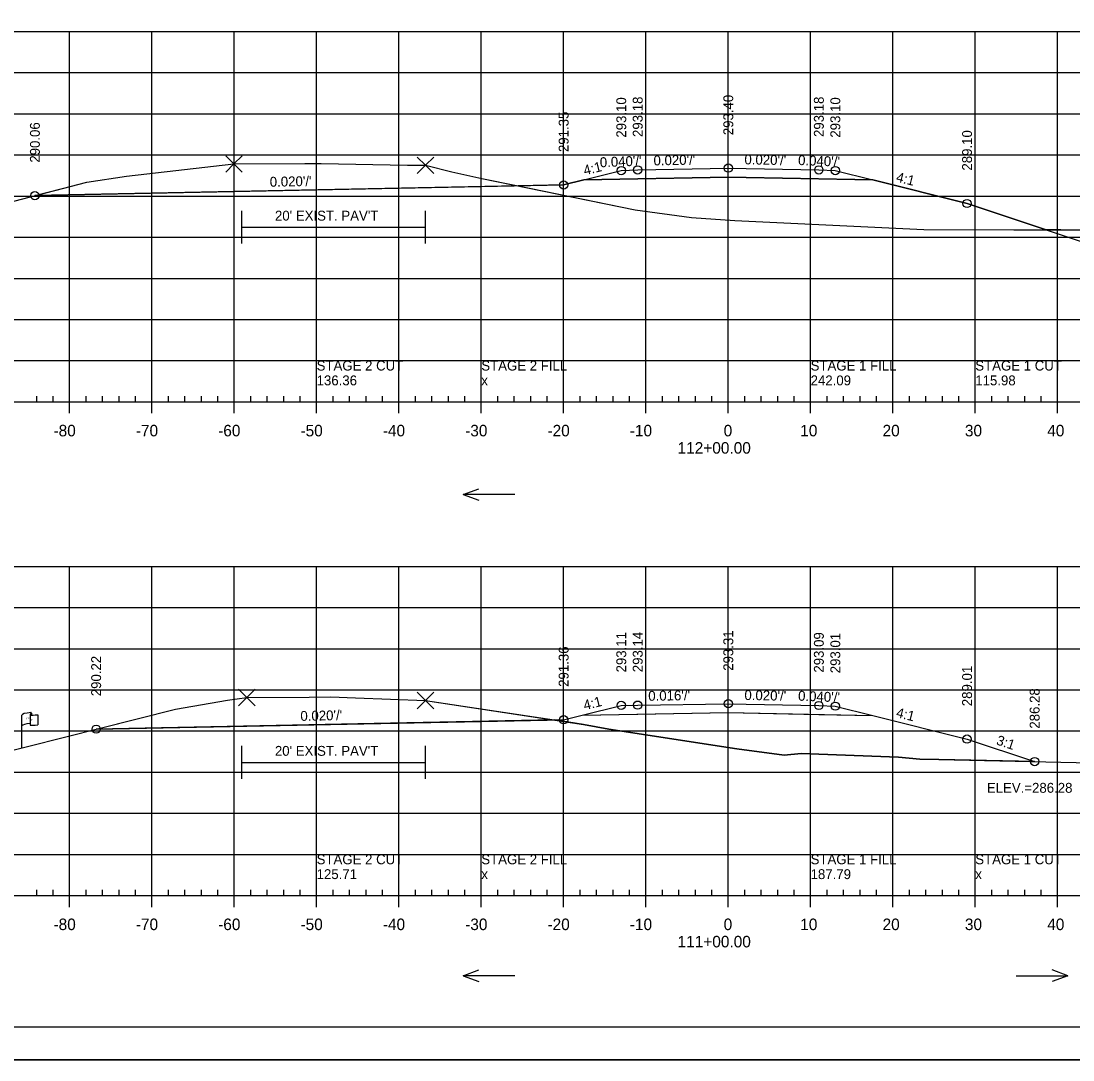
# Model space of a CAD drawing. Extents: x 1370843 to 1371177, y 380307 to 382654.
# Drawn here: x 1370927.8 to 1371055.6, y 381160.8 to 381287.1 of the extents above; entities that cross this region are included whole.
import ezdxf

# ---------------------------------------------------------------- set-up
doc = ezdxf.new("R2010")
doc.units = 0
for name, color, linetype in [('R_Alt Surface', 7, 'Continuous'), ('R_Axis', 7, 'Continuous'), ('R_Axis Annot', 7, 'Continuous'), ('R_Border', 7, 'Continuous'), ('R_Exist Surface', 7, 'Continuous'), ('R_Exist Surface Annot', 7, 'Continuous'), ('R_Fin Surface', 7, 'Continuous'), ('R_Fin Surface Annot', 7, 'Continuous'), ('R_Grid', 7, 'Continuous'), ('R_No Plot', 7, 'Continuous'), ('R_ROW', 7, 'Continuous'), ('R_Water Annot', 7, 'Continuous')]:
    doc.layers.add(name, color=color, linetype=linetype)

msp = doc.modelspace()

# ---------------------------------------------------------------- linework, layer by layer
at = {"layer": 'R_Alt Surface'}
for points in [[(1370996.17, 381267.76), (1371002.71, 381267.89), (1371013.71, 381268.11), (1371024.71, 381267.89), (1371031.25, 381267.76)], [(1370995.96, 381202.72), (1371002.71, 381202.86), (1371013.71, 381203.03), (1371024.71, 381202.81), (1371031.25, 381202.68)]]:
    msp.add_lwpolyline(points, dxfattribs=at)
at = {"layer": 'R_Axis'}
for p, q in [((1370929.71, 381240.8), (1370929.71, 381241.5)), ((1370931.71, 381240.8), (1370931.71, 381241.5)), ((1370935.71, 381240.8), (1370935.71, 381241.5)), ((1370937.71, 381240.8), (1370937.71, 381241.5)), ((1370939.71, 381240.8), (1370939.71, 381241.5)), ((1370941.71, 381240.8), (1370941.71, 381241.5)), ((1370945.71, 381240.8), (1370945.71, 381241.5)), ((1370947.71, 381240.8), (1370947.71, 381241.5)), ((1370949.71, 381240.8), (1370949.71, 381241.5)), ((1370951.71, 381240.8), (1370951.71, 381241.5)), ((1370955.71, 381240.8), (1370955.71, 381241.5)), ((1370957.71, 381240.8), (1370957.71, 381241.5)), ((1370959.71, 381240.8), (1370959.71, 381241.5)), ((1370961.71, 381240.8), (1370961.71, 381241.5)), ((1370965.71, 381240.8), (1370965.71, 381241.5)), ((1370967.71, 381240.8), (1370967.71, 381241.5)), ((1370969.71, 381240.8), (1370969.71, 381241.5)), ((1370971.71, 381240.8), (1370971.71, 381241.5)), ((1370975.71, 381240.8), (1370975.71, 381241.5)), ((1370977.71, 381240.8), (1370977.71, 381241.5)), ((1370979.71, 381240.8), (1370979.71, 381241.5)), ((1370981.71, 381240.8), (1370981.71, 381241.5)), ((1370985.71, 381240.8), (1370985.71, 381241.5)), ((1370987.71, 381240.8), (1370987.71, 381241.5)), ((1370989.71, 381240.8), (1370989.71, 381241.5)), ((1370991.71, 381240.8), (1370991.71, 381241.5)), ((1370995.71, 381240.8), (1370995.71, 381241.5)), ((1370997.71, 381240.8), (1370997.71, 381241.5)), ((1370999.71, 381240.8), (1370999.71, 381241.5)), ((1371001.71, 381240.8), (1371001.71, 381241.5)), ((1371005.71, 381240.8), (1371005.71, 381241.5)), ((1371007.71, 381240.8), (1371007.71, 381241.5)), ((1371009.71, 381240.8), (1371009.71, 381241.5)), ((1371011.71, 381240.8), (1371011.71, 381241.5)), ((1371015.71, 381240.8), (1371015.71, 381241.5)), ((1371017.71, 381240.8), (1371017.71, 381241.5)), ((1371019.71, 381240.8), (1371019.71, 381241.5)), ((1371021.71, 381240.8), (1371021.71, 381241.5)), ((1371025.71, 381240.8), (1371025.71, 381241.5)), ((1371027.71, 381240.8), (1371027.71, 381241.5)), ((1371029.71, 381240.8), (1371029.71, 381241.5)), ((1371031.71, 381240.8), (1371031.71, 381241.5)), ((1371035.71, 381240.8), (1371035.71, 381241.5)), ((1371037.71, 381240.8), (1371037.71, 381241.5)), ((1371039.71, 381240.8), (1371039.71, 381241.5)), ((1371041.71, 381240.8), (1371041.71, 381241.5)), ((1371045.71, 381240.8), (1371045.71, 381241.5)), ((1371047.71, 381240.8), (1371047.71, 381241.5)), ((1371049.71, 381240.8), (1371049.71, 381241.5)), ((1371051.71, 381240.8), (1371051.71, 381241.5)), ((1370868.71, 381240.8), (1371158.71, 381240.8)), ((1370933.71, 381239.4), (1370933.71, 381240.8)), ((1370943.71, 381239.4), (1370943.71, 381240.8)), ((1370953.71, 381239.4), (1370953.71, 381240.8)), ((1370963.71, 381239.4), (1370963.71, 381240.8)), ((1370973.71, 381239.4), (1370973.71, 381240.8)), ((1370983.71, 381239.4), (1370983.71, 381240.8)), ((1370993.71, 381239.4), (1370993.71, 381240.8)), ((1371003.71, 381239.4), (1371003.71, 381240.8)), ((1371013.71, 381239.4), (1371013.71, 381240.8)), ((1371023.71, 381239.4), (1371023.71, 381240.8)), ((1371033.71, 381239.4), (1371033.71, 381240.8)), ((1371043.71, 381239.4), (1371043.71, 381240.8)), ((1371053.71, 381239.4), (1371053.71, 381240.8)), ((1370929.71, 381180.8), (1370929.71, 381181.5)), ((1370931.71, 381180.8), (1370931.71, 381181.5)), ((1370935.71, 381180.8), (1370935.71, 381181.5)), ((1370937.71, 381180.8), (1370937.71, 381181.5)), ((1370939.71, 381180.8), (1370939.71, 381181.5)), ((1370941.71, 381180.8), (1370941.71, 381181.5)), ((1370945.71, 381180.8), (1370945.71, 381181.5)), ((1370947.71, 381180.8), (1370947.71, 381181.5)), ((1370949.71, 381180.8), (1370949.71, 381181.5)), ((1370951.71, 381180.8), (1370951.71, 381181.5)), ((1370955.71, 381180.8), (1370955.71, 381181.5)), ((1370957.71, 381180.8), (1370957.71, 381181.5)), ((1370959.71, 381180.8), (1370959.71, 381181.5)), ((1370961.71, 381180.8), (1370961.71, 381181.5)), ((1370965.71, 381180.8), (1370965.71, 381181.5)), ((1370967.71, 381180.8), (1370967.71, 381181.5)), ((1370969.71, 381180.8), (1370969.71, 381181.5)), ((1370971.71, 381180.8), (1370971.71, 381181.5)), ((1370975.71, 381180.8), (1370975.71, 381181.5)), ((1370977.71, 381180.8), (1370977.71, 381181.5)), ((1370979.71, 381180.8), (1370979.71, 381181.5)), ((1370981.71, 381180.8), (1370981.71, 381181.5)), ((1370985.71, 381180.8), (1370985.71, 381181.5)), ((1370987.71, 381180.8), (1370987.71, 381181.5)), ((1370989.71, 381180.8), (1370989.71, 381181.5)), ((1370991.71, 381180.8), (1370991.71, 381181.5)), ((1370995.71, 381180.8), (1370995.71, 381181.5)), ((1370997.71, 381180.8), (1370997.71, 381181.5)), ((1370999.71, 381180.8), (1370999.71, 381181.5)), ((1371001.71, 381180.8), (1371001.71, 381181.5)), ((1371005.71, 381180.8), (1371005.71, 381181.5)), ((1371007.71, 381180.8), (1371007.71, 381181.5)), ((1371009.71, 381180.8), (1371009.71, 381181.5)), ((1371011.71, 381180.8), (1371011.71, 381181.5)), ((1371015.71, 381180.8), (1371015.71, 381181.5)), ((1371017.71, 381180.8), (1371017.71, 381181.5)), ((1371019.71, 381180.8), (1371019.71, 381181.5)), ((1371021.71, 381180.8), (1371021.71, 381181.5)), ((1371025.71, 381180.8), (1371025.71, 381181.5)), ((1371027.71, 381180.8), (1371027.71, 381181.5)), ((1371029.71, 381180.8), (1371029.71, 381181.5)), ((1371031.71, 381180.8), (1371031.71, 381181.5)), ((1371035.71, 381180.8), (1371035.71, 381181.5)), ((1371037.71, 381180.8), (1371037.71, 381181.5)), ((1371039.71, 381180.8), (1371039.71, 381181.5)), ((1371041.71, 381180.8), (1371041.71, 381181.5)), ((1371045.71, 381180.8), (1371045.71, 381181.5)), ((1371047.71, 381180.8), (1371047.71, 381181.5)), ((1371049.71, 381180.8), (1371049.71, 381181.5)), ((1371051.71, 381180.8), (1371051.71, 381181.5)), ((1370868.71, 381180.8), (1371158.71, 381180.8)), ((1370933.71, 381179.4), (1370933.71, 381180.8)), ((1370943.71, 381179.4), (1370943.71, 381180.8)), ((1370953.71, 381179.4), (1370953.71, 381180.8)), ((1370963.71, 381179.4), (1370963.71, 381180.8)), ((1370973.71, 381179.4), (1370973.71, 381180.8)), ((1370983.71, 381179.4), (1370983.71, 381180.8)), ((1370993.71, 381179.4), (1370993.71, 381180.8)), ((1371003.71, 381179.4), (1371003.71, 381180.8)), ((1371013.71, 381179.4), (1371013.71, 381180.8)), ((1371023.71, 381179.4), (1371023.71, 381180.8)), ((1371033.71, 381179.4), (1371033.71, 381180.8)), ((1371043.71, 381179.4), (1371043.71, 381180.8)), ((1371053.71, 381179.4), (1371053.71, 381180.8))]:
    msp.add_line(p, q, dxfattribs=at)
at = {"layer": 'R_Border'}
msp.add_line((1371171.89, 381164.8), (1370855.71, 381164.8), dxfattribs=at)
at = {"layer": 'R_Exist Surface'}
for points in [[(1370868.71, 381261.19), (1370876.83, 381261.2), (1370877.3, 381261.19), (1370878.47, 381261.18), (1370908.87, 381260.52), (1370925.02, 381264.7), (1370935.81, 381267.51), (1370940.62, 381268.21), (1370953.67, 381269.71), (1370962.26, 381269.75), (1370964.28, 381269.75), (1370974.76, 381269.57), (1370976.93, 381269.54), (1370980.13, 381268.75), (1370983.76, 381267.94), (1371002.39, 381264.12), (1371009.24, 381263.19), (1371014.52, 381262.82), (1371037.46, 381261.75), (1371048.41, 381261.71), (1371054.1, 381261.68), (1371069.64, 381261.62)], [(1370924.06, 381197.79), (1370946.56, 381203.44), (1370952.9, 381204.53), (1370955.23, 381204.86), (1370962.79, 381204.92), (1370965.42, 381204.93), (1370968.43, 381204.81), (1370976.93, 381204.5), (1370991.6, 381202.28), (1370996.14, 381201.59), (1370999.19, 381201.03), (1371014.76, 381198.61), (1371020.51, 381197.85), (1371022.55, 381198.07), (1371034.39, 381197.61), (1371036.96, 381197.36), (1371039.3, 381197.33), (1371057.83, 381196.93)]]:
    msp.add_lwpolyline(points, dxfattribs=at)
at = {"layer": 'R_Exist Surface Annot'}
for p, q in [((1370954.64, 381260.02), (1370954.64, 381264.02)), ((1370976.93, 381260.02), (1370976.93, 381264.02)), ((1370954.64, 381262.02), (1370976.93, 381262.02)), ((1370954.64, 381194.98), (1370954.64, 381198.98)), ((1370976.93, 381194.98), (1370976.93, 381198.98)), ((1370954.64, 381196.98), (1370976.93, 381196.98))]:
    msp.add_line(p, q, dxfattribs=at)
at = {"layer": 'R_Fin Surface'}
for points in [[(1370929.49, 381265.86), (1370983.71, 381266.95), (1370993.71, 381267.15), (1370996.17, 381267.76), (1371000.71, 381268.9), (1371002.71, 381268.98), (1371013.71, 381269.2), (1371024.71, 381268.98), (1371026.71, 381268.9), (1371031.25, 381267.76), (1371042.71, 381264.9), (1371071.42, 381255.33), (1371088.94, 381261.17)], [(1370936.93, 381201.02), (1370983.71, 381201.96), (1370993.71, 381202.16), (1370995.96, 381202.72), (1371000.71, 381203.91), (1371002.71, 381203.94), (1371013.71, 381204.11), (1371024.71, 381203.89), (1371026.71, 381203.81), (1371031.25, 381202.68), (1371042.71, 381199.81), (1371050.92, 381197.08)]]:
    msp.add_lwpolyline(points, dxfattribs=at)
at = {"layer": 'R_Grid'}
for p, q in [((1370868.71, 381285.8), (1371158.71, 381285.8)), ((1370933.71, 381240.8), (1370933.71, 381285.8)), ((1370943.71, 381240.8), (1370943.71, 381285.8)), ((1370953.71, 381240.8), (1370953.71, 381285.8)), ((1370963.71, 381240.8), (1370963.71, 381285.8)), ((1370973.71, 381240.8), (1370973.71, 381285.8)), ((1370983.71, 381240.8), (1370983.71, 381285.8)), ((1370993.71, 381240.8), (1370993.71, 381285.8)), ((1371003.71, 381240.8), (1371003.71, 381285.8)), ((1371013.71, 381240.8), (1371013.71, 381285.8)), ((1371023.71, 381240.8), (1371023.71, 381285.8)), ((1371033.71, 381240.8), (1371033.71, 381285.8)), ((1371043.71, 381240.8), (1371043.71, 381285.8)), ((1371053.71, 381240.8), (1371053.71, 381285.8)), ((1370868.71, 381280.8), (1371158.71, 381280.8)), ((1370868.71, 381275.8), (1371158.71, 381275.8)), ((1370868.71, 381270.8), (1371158.71, 381270.8)), ((1370868.71, 381265.8), (1371158.71, 381265.8)), ((1370868.71, 381260.8), (1371158.71, 381260.8)), ((1370868.71, 381255.8), (1371158.71, 381255.8)), ((1370868.71, 381250.8), (1371158.71, 381250.8)), ((1370868.71, 381245.8), (1371158.71, 381245.8)), ((1370868.71, 381240.8), (1371158.71, 381240.8)), ((1370868.71, 381220.8), (1371158.71, 381220.8)), ((1370933.71, 381180.8), (1370933.71, 381220.8)), ((1370943.71, 381180.8), (1370943.71, 381220.8)), ((1370953.71, 381180.8), (1370953.71, 381220.8)), ((1370963.71, 381180.8), (1370963.71, 381220.8)), ((1370973.71, 381180.8), (1370973.71, 381220.8)), ((1370983.71, 381180.8), (1370983.71, 381220.8)), ((1370993.71, 381180.8), (1370993.71, 381220.8)), ((1371003.71, 381180.8), (1371003.71, 381220.8)), ((1371013.71, 381180.8), (1371013.71, 381220.8)), ((1371023.71, 381180.8), (1371023.71, 381220.8)), ((1371033.71, 381180.8), (1371033.71, 381220.8)), ((1371043.71, 381180.8), (1371043.71, 381220.8)), ((1371053.71, 381180.8), (1371053.71, 381220.8)), ((1370868.71, 381215.8), (1371158.71, 381215.8)), ((1370868.71, 381210.8), (1371158.71, 381210.8)), ((1370868.71, 381205.8), (1371158.71, 381205.8)), ((1370868.71, 381200.8), (1371158.71, 381200.8)), ((1370868.71, 381195.8), (1371158.71, 381195.8)), ((1370868.71, 381190.8), (1371158.71, 381190.8)), ((1370868.71, 381185.8), (1371158.71, 381185.8)), ((1370868.71, 381180.8), (1371158.71, 381180.8))]:
    msp.add_line(p, q, dxfattribs=at)
at = {"layer": 'R_No Plot'}
msp.add_line((1370843.31, 381160.82), (1371176.64, 381160.82), dxfattribs=at)
for points in [[(1370843.3, 381374.15), (1371176.64, 381374.15), (1371176.64, 381160.82), (1370843.3, 381160.82)], [(1371089.63, 381370.26), (1371089.63, 381360.38), (1371125.36, 381360.38), (1371125.36, 381357.46), (1371148.56, 381357.46), (1371148.56, 381333.13), (1371171.89, 381333.13), (1371171.89, 381164.8), (1370855.71, 381164.8), (1370855.71, 381370.26)], [(1370929.49, 381265.86), (1370935.81, 381267.51), (1370940.62, 381268.21), (1370953.67, 381269.71), (1370962.26, 381269.75), (1370964.28, 381269.75), (1370974.76, 381269.57), (1370976.93, 381269.54), (1370980.13, 381268.75), (1370983.76, 381267.94), (1370988.18, 381267.04)], [(1370988.18, 381267.04), (1371002.39, 381264.12), (1371009.24, 381263.19), (1371014.52, 381262.82), (1371037.46, 381261.75), (1371048.41, 381261.71), (1371052.33, 381261.69), (1371042.71, 381264.9), (1371031.25, 381267.76), (1371013.71, 381268.11), (1370996.17, 381267.76), (1370993.71, 381267.15)], [(1371052.33, 381261.69), (1371071.42, 381255.33), (1371088.94, 381261.17), (1371076.1, 381261.6), (1371073.16, 381261.61), (1371069.64, 381261.62), (1371054.1, 381261.68)], [(1370936.93, 381201.02), (1370946.56, 381203.44), (1370952.9, 381204.53), (1370955.23, 381204.86), (1370962.79, 381204.92), (1370965.42, 381204.93), (1370968.43, 381204.81), (1370976.93, 381204.5), (1370992.56, 381202.14)], [(1370992.56, 381202.14), (1370993.71, 381202.16), (1370995.96, 381202.72), (1371013.71, 381203.03), (1371031.25, 381202.68), (1371042.71, 381199.81), (1371050.92, 381197.08), (1371039.3, 381197.33), (1371036.96, 381197.36), (1371034.39, 381197.61), (1371022.55, 381198.07), (1371020.51, 381197.85), (1371014.76, 381198.61), (1370999.19, 381201.03), (1370996.14, 381201.59)]]:
    msp.add_lwpolyline(points, close=True, dxfattribs=at)
for points in [[(1370953.67, 381269.71), (1370952.67, 381270.71), (1370953.67, 381269.71), (1370952.67, 381268.71), (1370953.67, 381269.71), (1370954.67, 381268.71), (1370953.67, 381269.71), (1370954.67, 381270.71)], [(1370976.93, 381269.54), (1370975.93, 381270.54), (1370976.93, 381269.54), (1370975.93, 381268.54), (1370976.93, 381269.54), (1370977.93, 381268.54), (1370976.93, 381269.54), (1370977.93, 381270.54)], [(1370955.23, 381204.86), (1370954.23, 381205.86), (1370955.23, 381204.86), (1370954.23, 381203.86), (1370955.23, 381204.86), (1370956.23, 381203.86), (1370955.23, 381204.86), (1370956.23, 381205.86)], [(1370976.93, 381204.5), (1370975.93, 381205.5), (1370976.93, 381204.5), (1370975.93, 381203.5), (1370976.93, 381204.5), (1370977.93, 381203.5), (1370976.93, 381204.5), (1370977.93, 381205.5)]]:
    msp.add_lwpolyline(points, dxfattribs=at)
for centre in [(1371000.71, 381268.9), (1371002.71, 381268.98), (1371013.71, 381269.2), (1371024.71, 381268.98), (1371026.71, 381268.9), (1370993.71, 381267.15), (1370929.49, 381265.86), (1371042.71, 381264.9), (1371000.71, 381203.91), (1371002.71, 381203.94), (1371013.71, 381204.11), (1371024.71, 381203.89), (1371026.71, 381203.81), (1370936.93, 381201.02), (1370993.71, 381202.16), (1371042.71, 381199.81), (1371050.92, 381197.08)]:
    msp.add_circle(centre, 0.5, dxfattribs=at)
at = {"layer": 'R_ROW'}
for p, q in [((1370927.91, 381198.76), (1370927.91, 381202.71)), ((1370928.9, 381202.8), (1370928.9, 381202.79)), ((1370928.9, 381202.79), (1370928.9, 381201.56)), ((1370929.07, 381202.96), (1370929.07, 381202.72)), ((1370929.84, 381202.77), (1370929.84, 381201.53))]:
    msp.add_line(p, q, dxfattribs=at)
for centre, radius, start, end in [((1370928.98, 381202.81), 0.078, 88.6458, 274.2828), ((1370928.99, 381202.96), 0.0783, 263.0712, 93.9564), ((1370928.98, 381201.56), 0.0783, 180, 273.9564)]:
    msp.add_arc(centre, radius, start, end, dxfattribs=at)
for centre, major_axis, ratio, start_param, end_param in [((1370929.49, 381202.75), (-1.58, -0.04), 0.19887, 5.030368, 6.283185), ((1370930.2, 381202.87), (-1.23, -0.13), 0.052933, 0.159456, 1.268315), ((1370929.49, 381201.44), (-1.58, -0.04), 0.19887, 5.083035, 6.194897), ((1370930.2, 381201.63), (-1.23, -0.13), 0.052933, 0.159456, 1.268315)]:
    msp.add_ellipse(centre, major_axis=major_axis, ratio=ratio, start_param=start_param, end_param=end_param, dxfattribs=at)
at = {"layer": 'R_Water Annot'}
for p, q in [((1370981.5, 381229.53), (1370983.42, 381230.23)), ((1370987.78, 381229.53), (1370981.5, 381229.53)), ((1370981.5, 381229.53), (1370983.42, 381228.83)), ((1370981.5, 381171.06), (1370983.42, 381171.76)), ((1370987.78, 381171.06), (1370981.5, 381171.06)), ((1370981.5, 381171.06), (1370983.42, 381170.36)), ((1371048.67, 381171.06), (1371054.96, 381171.06)), ((1371054.96, 381171.06), (1371053.04, 381171.76)), ((1371054.96, 381171.06), (1371053.04, 381170.36))]:
    msp.add_line(p, q, dxfattribs=at)

# ---------------------------------------------------------------- texts
at = {"layer": 'R_Axis Annot'}
for s, p in [('-80', (1370931.75, 381236.6)), ('-70', (1370941.75, 381236.6)), ('-60', (1370951.75, 381236.6)), ('-50', (1370961.75, 381236.6)), ('-40', (1370971.75, 381236.6)), ('-30', (1370981.75, 381236.6)), ('-20', (1370991.75, 381236.6)), ('-10', (1371001.75, 381236.6)), ('0', (1371013.15, 381236.6)), ('10', (1371022.45, 381236.6)), ('20', (1371032.45, 381236.6)), ('30', (1371042.45, 381236.6)), ('40', (1371052.45, 381236.6)), ('112+00.00', (1371007.55, 381234.5)), ('-80', (1370931.75, 381176.6)), ('-70', (1370941.75, 381176.6)), ('-60', (1370951.75, 381176.6)), ('-50', (1370961.75, 381176.6)), ('-40', (1370971.75, 381176.6)), ('-30', (1370981.75, 381176.6)), ('-20', (1370991.75, 381176.6)), ('-10', (1371001.75, 381176.6)), ('0', (1371013.15, 381176.6)), ('10', (1371022.45, 381176.6)), ('20', (1371032.45, 381176.6)), ('30', (1371042.45, 381176.6)), ('40', (1371052.45, 381176.6)), ('111+00.00', (1371007.55, 381174.5))]:
    msp.add_text(s, height=1.4, dxfattribs=at).set_placement(p)
at = {"layer": 'R_Exist Surface Annot'}
for p in [(1370958.65, 381262.82), (1370958.64, 381197.78)]:
    msp.add_text("20' EXIST. PAV'T", height=1.2, dxfattribs=at).set_placement(p)
at = {"layer": 'R_Fin Surface Annot'}
for s, rotation, p in [('293.10', 90, (1371001.31, 381272.9)), ('293.18', 90, (1371003.31, 381272.98)), ('293.40', 90, (1371014.31, 381273.2)), ('293.18', 90, (1371025.31, 381272.98)), ('293.10', 90, (1371027.31, 381272.9)), ('291.35', 90, (1370994.31, 381271.15)), ('290.06', 90, (1370930.09, 381269.86)), ('289.10', 90, (1371043.31, 381268.9)), ("0.040'/'", 2.2906, (1370998.13, 381269.3)), ("0.020'/'", 1.1458, (1371004.64, 381269.52)), ("0.020'/'", 358.8542, (1371015.66, 381269.66)), ("0.040'/'", 357.7094, (1371022.17, 381269.58)), ('4:1', 14.0362, (1370996.28, 381268.31)), ("0.020'/'", 1.1458, (1370958.03, 381266.93)), ('4:1', 345.9638, (1371034.02, 381267.58)), ('293.31', 90, (1371014.31, 381208.11)), ('293.11', 90, (1371001.31, 381207.91)), ('293.14', 90, (1371003.31, 381207.94)), ('293.09', 90, (1371025.31, 381207.89)), ('293.01', 90, (1371027.31, 381207.81)), ('291.36', 90, (1370994.31, 381206.16)), ('290.22', 90, (1370937.53, 381205.02)), ('289.01', 90, (1371043.31, 381203.81)), ("0.016'/'", 0.8913, (1371004, 381204.46)), ("0.020'/'", 358.8542, (1371015.66, 381204.57)), ("0.040'/'", 357.7094, (1371022.17, 381204.49)), ('286.28', 90, (1371051.52, 381201.08)), ('4:1', 14.0362, (1370996.28, 381203.32)), ("0.020'/'", 1.1458, (1370961.75, 381202.02)), ('4:1', 345.9638, (1371034.02, 381202.5)), ('3:1', 341.5651, (1371046.18, 381199.18))]:
    msp.add_text(s, height=1.2, rotation=rotation, dxfattribs=at).set_placement(p)
at = {"layer": 'R_No Plot'}
for s, p in [('STAGE 2 CUT', (1370963.71, 381244.6)), ('STAGE 2 FILL', (1370983.71, 381244.6)), ('STAGE 1 FILL', (1371023.71, 381244.6)), ('STAGE 1 CUT', (1371043.71, 381244.6)), ('136.36', (1370963.71, 381242.8)), ('x', (1370983.71, 381242.8)), ('242.09', (1371023.71, 381242.8)), ('115.98', (1371043.71, 381242.8)), ('STAGE 2 CUT', (1370963.71, 381184.6)), ('STAGE 2 FILL', (1370983.71, 381184.6)), ('STAGE 1 FILL', (1371023.71, 381184.6)), ('STAGE 1 CUT', (1371043.71, 381184.6)), ('125.71', (1370963.71, 381182.8)), ('x', (1370983.71, 381182.8)), ('187.79', (1371023.71, 381182.8)), ('x', (1371043.71, 381182.8))]:
    msp.add_text(s, height=1.2, dxfattribs=at).set_placement(p)
at = {"layer": 'R_ROW'}
for s, height, rotation, p in [('DWB 11-9-07', 0.001, 90, (1370929.07, 381202.72)), ('R ', 0.2, 9.9884, (1370928.43, 381202.21)), (' O', 0.2, 9.9884, (1370928.57, 381202.26)), ('W', 0.2, 351.1788, (1370928.9, 381202.09)), ('DWB 11-9-07', 0.001, 5.0717, (1370929.83, 381201.53)), ('DWB 11-9-07', 0.001, 90, (1370927.91, 381198.76))]:
    msp.add_text(s, height=height, rotation=rotation, dxfattribs=at).set_placement(p)
at = {"layer": 'R_Water Annot'}
msp.add_text('ELEV.=286.28', height=1.2, dxfattribs=at).set_placement((1371045.12, 381193.29))

doc.saveas('drawing.dxf')
